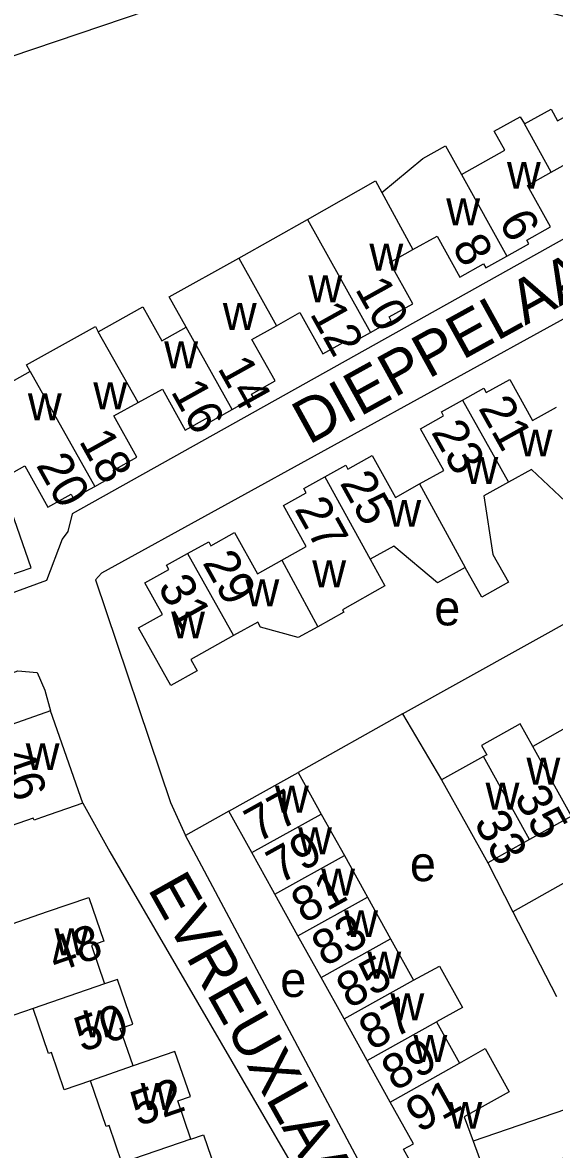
# Model space of a CAD drawing. Extents: x 157768 to 159790, y 387230 to 389604.
# Drawn here: x 159010.1 to 159070.9, y 389220.4 to 389349.2 of the extents above; entities that cross this region are included whole.
import ezdxf

# ---------------------------------------------------------------- set-up
doc = ezdxf.new("R2010")
doc.units = 0
for name, color, linetype in [('BLT_Basislijn', 7, 'Continuous'), ('BLT_Bebouwing', 7, 'Continuous'), ('BLT_Centroide', 7, 'Continuous'), ('BLT_Huisnummer', 7, 'Continuous'), ('BLT_Huisnummer_ tussenligend', 7, 'Continuous'), ('BLT_Onderverdeling_panden', 7, 'Continuous'), ('BLT_Straatnaam', 7, 'Continuous')]:
    doc.layers.add(name, color=color, linetype=linetype)

msp = doc.modelspace()

# ---------------------------------------------------------------- linework, layer by layer
at = {"layer": 'BLT_Basislijn'}
for p, q in [((159053.5, 389270.2), (159041.58, 389263.5)), ((159053.5, 389270.2), (159057.96, 389262.65)), ((159033.64, 389259.09), (159028.71, 389256.3)), ((159051.51, 389213.49), (159028.71, 389256.3)), ((159063.24, 389253.18), (159066.11, 389247.59)), ((159066.11, 389247.59), (159071.09, 389237.9))]:
    msp.add_line(p, q, dxfattribs=at)
for points in [[(159081.17, 389347.4), (159062.62, 389352.37), (159040.89, 389355.96), (159039.92, 389355.84), (158953.96, 389326.76), (158921.99, 389315.64)], [(159100, 389340.14), (159015.73, 389293.05), (159015.24, 389291.03), (159014.6, 389290.14), (159012.8, 389285.42), (158959.78, 389266), (158951.5, 389263.29), (158928.72, 389290.57)], [(159085.56, 389322.83), (159019.11, 389286.26), (159018.43, 389285.49), (159026.99, 389260.06), (159028.71, 389256.3)], [(159053.5, 389270.2), (159088.11, 389289.43), (159100.52, 389303.13)], [(159118.07, 389274.1), (159116.3, 389275.42), (159115.61, 389275.31), (159100, 389266.67), (159066.11, 389247.59)], [(158956.38, 389249.06), (158954.45, 389254.84), (159009.52, 389275.09), (159011.75, 389274.93), (159012.61, 389272.91), (159013.28, 389270.53)], [(159016.96, 389259.99), (159020.06, 389254.43), (159042.79, 389215.35), (159049.71, 389196.11), (159050.24, 389192.78), (159048.42, 389190.5), (159046.46, 389189.7), (159011.37, 389177.96)], [(159077.13, 389227.04), (159072.12, 389225), (159061.57, 389221.39)]]:
    msp.add_lwpolyline(points, dxfattribs=at)
at = {"layer": 'BLT_Bebouwing'}
for p, q in [((159016.96, 389259.99), (159013.28, 389270.53)), ((159073.17, 389269.15), (159068.38, 389266.48)), ((159033.64, 389259.09), (159041.58, 389263.5)), ((159041.58, 389263.5), (159044.22, 389258.75)), ((159036.28, 389254.34), (159033.64, 389259.09)), ((159044.22, 389258.75), (159046.86, 389254)), ((159072.82, 389258.52), (159068.03, 389255.85)), ((159068.03, 389255.85), (159063.24, 389253.18)), ((159041.55, 389244.84), (159038.91, 389249.59)), ((159049.49, 389249.25), (159052.13, 389244.5)), ((159044.19, 389240.09), (159041.55, 389244.84)), ((159052.13, 389244.5), (159054.77, 389239.76)), ((159046.82, 389235.34), (159044.19, 389240.09)), ((159049.46, 389230.6), (159046.82, 389235.34)), ((159057.4, 389235.01), (159060.02, 389230.3)), ((159052.1, 389225.85), (159049.46, 389230.6)), ((159017.85, 389228.29), (159014.85, 389227.26)), ((159054.74, 389221.09), (159052.1, 389225.85)), ((159060.56, 389224.15), (159061.57, 389221.39))]:
    msp.add_line(p, q, dxfattribs=at)
for points in [[(159067.44, 389337.58), (159070.48, 389339.28), (159071.23, 389337.94), (159075.95, 389340.58)], [(159060.23, 389331.82), (159065.2, 389334.59), (159063.99, 389336.76), (159066.95, 389338.41), (159067.44, 389337.58)], [(159051.13, 389329.76), (159055.81, 389333.62), (159058.42, 389335.08), (159060.23, 389331.82)], [(159070.51, 389332.08), (159073.24, 389333.59), (159075.86, 389328.88), (159078.57, 389330.39), (159078.82, 389329.95), (159081.14, 389331.24)], [(159065.43, 389322.48), (159067.95, 389323.89), (159067.71, 389324.32), (159070.43, 389325.83), (159067.79, 389330.56), (159070.51, 389332.08)], [(159042.65, 389326.65), (159050.4, 389331.1), (159051.13, 389329.76)], [(159034.78, 389322.26), (159042.65, 389326.65)], [(159054.67, 389323.22), (159057.45, 389324.77), (159060.06, 389320.09), (159062.77, 389321.6), (159063.03, 389321.14), (159065.43, 389322.48)], [(159049.83, 389313.77), (159052.22, 389315.1), (159051.98, 389315.54), (159054.67, 389317.03), (159052.04, 389321.75), (159054.67, 389323.22)], [(159028.79, 389314.35), (159026.85, 389317.84), (159034.78, 389322.26)], [(159018.73, 389313.85), (159023.84, 389316.7), (159026.01, 389312.8), (159028.79, 389314.35)], [(159039.09, 389314.53), (159041.78, 389316.03), (159044.41, 389311.31), (159047.07, 389312.79), (159047.31, 389312.36), (159049.83, 389313.77)], [(159010.95, 389309.32), (159010.53, 389310.07), (159018.4, 389314.45), (159018.73, 389313.85)], [(159034.02, 389304.96), (159036.46, 389306.32), (159036.24, 389306.72), (159038.93, 389308.22), (159036.29, 389312.97), (159039.09, 389314.53)], [(159010.95, 389309.32), (159006.64, 389306.92), (159006.06, 389307.97), (159003.06, 389306.3), (159004.37, 389302.5), (159007.43, 389297.01)], [(159060.37, 389306.04), (159062.8, 389307.39), (159063.07, 389306.9), (159065.75, 389308.39), (159068.36, 389303.72), (159071.09, 389305.24)], [(159023.29, 389305.76), (159026.06, 389307.3), (159028.68, 389302.59), (159031.33, 389304.07), (159031.59, 389303.6), (159034.02, 389304.96)], [(159018.32, 389296.18), (159020.7, 389297.51), (159020.43, 389297.99), (159023.15, 389299.5), (159020.52, 389304.22), (159023.29, 389305.76)], [(159055.46, 389296.46), (159058.21, 389297.99), (159055.54, 389302.77), (159058.2, 389304.25), (159057.95, 389304.68), (159060.37, 389306.04)], [(159007.57, 389296.96), (159010.35, 389298.51), (159012.97, 389293.81), (159015.62, 389295.29), (159015.88, 389294.82), (159018.32, 389296.18)], [(159044.63, 389297.27), (159047.02, 389298.6), (159047.27, 389298.14), (159050.05, 389299.69), (159052.71, 389294.92), (159055.46, 389296.46)], [(159039.72, 389287.75), (159042.5, 389289.3), (159039.89, 389293.98), (159042.51, 389295.44), (159042.24, 389295.93), (159044.63, 389297.27)], [(159076.74, 389295.09), (159073.43, 389293.25), (159068.24, 389298.12), (159065.61, 389296.65)], [(159000.69, 389289.61), (159003.44, 389290.57), (159005.23, 389285.44), (159008.19, 389286.47), (159008.38, 389285.95), (159011.08, 389286.89), (159007.57, 389296.96)], [(159065.61, 389296.65), (159062.8, 389295.09), (159063.83, 389288.4), (159065.6, 389285.22), (159062.55, 389283.51), (159060.65, 389286.91)], [(159028.94, 389288.52), (159031.35, 389289.86), (159031.61, 389289.4), (159034.31, 389290.91), (159036.94, 389286.2), (159039.72, 389287.75)], [(159034.18, 389279.13), (159029.3, 389276.4), (159030.02, 389275.09), (159027.02, 389273.42), (159023.34, 389280.01), (159026.09, 389281.54), (159024.07, 389285.17), (159026.8, 389286.69), (159026.53, 389287.17), (159028.94, 389288.52)], [(159060.65, 389286.91), (159057.49, 389285.15), (159052.52, 389289.36), (159049.81, 389287.86)], [(159049.81, 389287.86), (159051.5, 389284.81), (159046.64, 389282.09), (159046.79, 389281.81), (159043.82, 389280.15)], [(159043.82, 389280.15), (159041.57, 389278.9), (159037.28, 389280.11), (159036.97, 389280.68), (159034.18, 389279.13)], [(159013.28, 389270.53), (159008.2, 389268.75), (159008.68, 389267.36), (159003.91, 389265.7)], [(159068.38, 389266.48), (159066.95, 389269.05), (159062.54, 389266.59), (159063.13, 389265.53), (159062.75, 389265.32)], [(159062.75, 389265.32), (159057.96, 389262.65)], [(159057.96, 389262.65), (159060.8, 389257.55), (159063.24, 389253.18)], [(159016.96, 389259.99), (159012.24, 389258.34), (159011.39, 389258.04), (159011.3, 389258.29), (159006.98, 389256.79)], [(159038.91, 389249.59), (159038.69, 389250), (159036.28, 389254.34)], [(159046.86, 389254), (159049.08, 389250), (159049.49, 389249.25)], [(159011.29, 389236.54), (159007.97, 389235.39), (159004.73, 389244.78), (159008.02, 389245.91), (159012.92, 389247.6), (159017.65, 389249.23), (159019.37, 389244.23), (159017.94, 389243.74), (159019.45, 389239.35)], [(159054.77, 389239.76), (159057.73, 389241.37), (159060.35, 389236.65), (159057.4, 389235.01)], [(159022.71, 389229.97), (159021.23, 389234.27), (159022.67, 389234.76), (159020.92, 389239.85), (159019.45, 389239.35)], [(159014.85, 389227.26), (159013.38, 389231.51), (159013.06, 389231.4), (159011.29, 389236.54)], [(159029.32, 389221.61), (159027.81, 389225.98), (159029.26, 389226.48), (159027.49, 389231.61), (159022.71, 389229.97)], [(159060.02, 389230.3), (159062.96, 389231.95), (159065.71, 389227.01), (159060.56, 389224.15)], [(159021.44, 389218.89), (159019.96, 389223.18), (159019.64, 389223.07), (159017.85, 389228.29)], [(159029.32, 389221.61), (159030.75, 389222.1), (159032.51, 389217.01), (159031.11, 389216.53), (159032.71, 389211.9), (159027.98, 389210.27), (159023.88, 389208.86), (159022.31, 389213.42), (159017.88, 389211.9), (159016.12, 389217.01), (159021.44, 389218.89)], [(159061.57, 389221.39), (159062.99, 389217.55), (159056.5, 389215.28)], [(159056.5, 389215.28), (159053.6, 389220.46), (159054.74, 389221.09)]]:
    msp.add_lwpolyline(points, dxfattribs=at)
at = {"layer": 'BLT_Onderverdeling_panden'}
for p, q in [((159070.51, 389332.08), (159067.44, 389337.58)), ((159060.23, 389331.82), (159065.43, 389322.48)), ((159051.13, 389329.76), (159054.67, 389323.22)), ((159042.65, 389326.65), (159049.83, 389313.77)), ((159034.78, 389322.26), (159039.09, 389314.53)), ((159034.02, 389304.96), (159028.79, 389314.35)), ((159023.29, 389305.76), (159018.73, 389313.85)), ((159010.95, 389309.32), (159018.32, 389296.18)), ((159060.37, 389306.04), (159065.61, 389296.65)), ((159044.63, 389297.27), (159049.81, 389287.86)), ((159055.46, 389296.46), (159060.65, 389286.91)), ((159028.94, 389288.52), (159034.18, 389279.13)), ((159039.72, 389287.75), (159043.82, 389280.15)), ((159072.82, 389258.52), (159068.38, 389266.48)), ((159068.03, 389255.85), (159062.75, 389265.32)), ((159036.28, 389254.34), (159044.22, 389258.75)), ((159038.91, 389249.59), (159046.86, 389254)), ((159041.55, 389244.84), (159049.49, 389249.25)), ((159044.19, 389240.09), (159052.13, 389244.5)), ((159019.45, 389239.35), (159011.29, 389236.54)), ((159046.82, 389235.34), (159054.77, 389239.76)), ((159049.46, 389230.6), (159057.4, 389235.01)), ((159052.1, 389225.85), (159060.02, 389230.3)), ((159022.71, 389229.97), (159017.85, 389228.29)), ((159029.32, 389221.61), (159021.44, 389218.89))]:
    msp.add_line(p, q, dxfattribs=at)

# ---------------------------------------------------------------- texts
at = {"layer": 'BLT_Centroide'}
for s, p in [('w', (159065.44, 389330.17)), ('w', (159058.5, 389326)), ('w', (159049.72, 389320.83)), ('w', (159042.75, 389317.22)), ('w', (159032.97, 389314.05)), ('w', (159026.27, 389309.66)), ('w', (159018.17, 389304.98)), ('w', (159010.69, 389303.73)), ('w', (159066.77, 389299.6)), ('w', (159060.58, 389296.47)), ('w', (159051.77, 389291.56)), ('w', (159043.19, 389284.65)), ('w', (159035.55, 389282.48)), ('e', (159057.13, 389280.3)), ('w', (159027.06, 389278.81)), ('w', (159010.44, 389263.77)), ('w', (159067.67, 389262.11)), ('w', (159038.93, 389258.91)), ('w', (159063, 389259.25)), ('w', (159041.57, 389254.16)), ('e', (159054.35, 389251.08)), ('w', (159044.21, 389249.44)), ('w', (159046.84, 389244.69)), ('w', (159013.73, 389242.62)), ('w', (159049.48, 389239.94)), ('e', (159039.53, 389237.86)), ('w', (159052.12, 389235.19)), ('w', (159017.02, 389233.25)), ('w', (159054.75, 389230.44)), ('w', (159023.58, 389224.95)), ('w', (159058.75, 389222.8))]:
    msp.add_text(s, height=4, dxfattribs=at).set_placement(p)
at = {"layer": 'BLT_Huisnummer'}
for s, rotation, p in [('6', 299.1288, (159064.43, 389326.42)), ('10', 299.1288, (159048.02, 389318.74)), ('14', 299.1288, (159032.3, 389309.7)), ('21', 299.1576, (159062.11, 389305.13)), ('20', 299.1288, (159011.56, 389298.61)), ('25', 299.1576, (159046.28, 389296.57)), ('31', 299.1576, (159025.46, 389284.71)), ('46', 288.9991, (159007.26, 389265.57)), ('77', 29.0362, (159036.93, 389255.41)), ('33', 299.1212, (159061.59, 389257.78)), ('81', 29.0362, (159042.26, 389246.17)), ('48', 19.0011, (159013.87, 389240.61)), ('85', 29.0362, (159047.42, 389236.45)), ('91', 29.0362, (159055.37, 389222.28))]:
    msp.add_text(s, height=4, rotation=rotation, dxfattribs=at).set_placement(p)
at = {"layer": 'BLT_Huisnummer_ tussenligend'}
for s, rotation, p in [('8', 299.1288, (159059.1, 389323.59)), ('12', 299.1288, (159042.85, 389315.91)), ('16', 299.1288, (159026.96, 389307.03)), ('23', 299.1576, (159056.72, 389302.39)), ('18', 299.1288, (159016.46, 389301.37)), ('27', 299.1576, (159041.1, 389293.6)), ('29', 299.1576, (159030.59, 389287.47)), ('35', 299.1212, (159066.2, 389260.67)), ('79', 29.0362, (159039.45, 389250.7)), ('83', 29.0362, (159044.61, 389241.24)), ('50', 19.0011, (159016.85, 389231.51)), ('87', 29.0362, (159050, 389231.66)), ('89', 29.0362, (159052.59, 389227.03)), ('52', 19.0011, (159023.29, 389223.04))]:
    msp.add_text(s, height=4, rotation=rotation, dxfattribs=at).set_placement(p)
at = {"layer": 'BLT_Straatnaam'}
for s, rotation, p in [('DIEPPELAAN', 28.9017, (159042.8, 389300.88)), ('EVREUXLAAN', 299.384, (159024.31, 389250.21)), ('EVREUXLAAN', 19.6643, (159058.89, 389209.57))]:
    msp.add_text(s, height=5, rotation=rotation, dxfattribs=at).set_placement(p)

doc.saveas('drawing.dxf')
